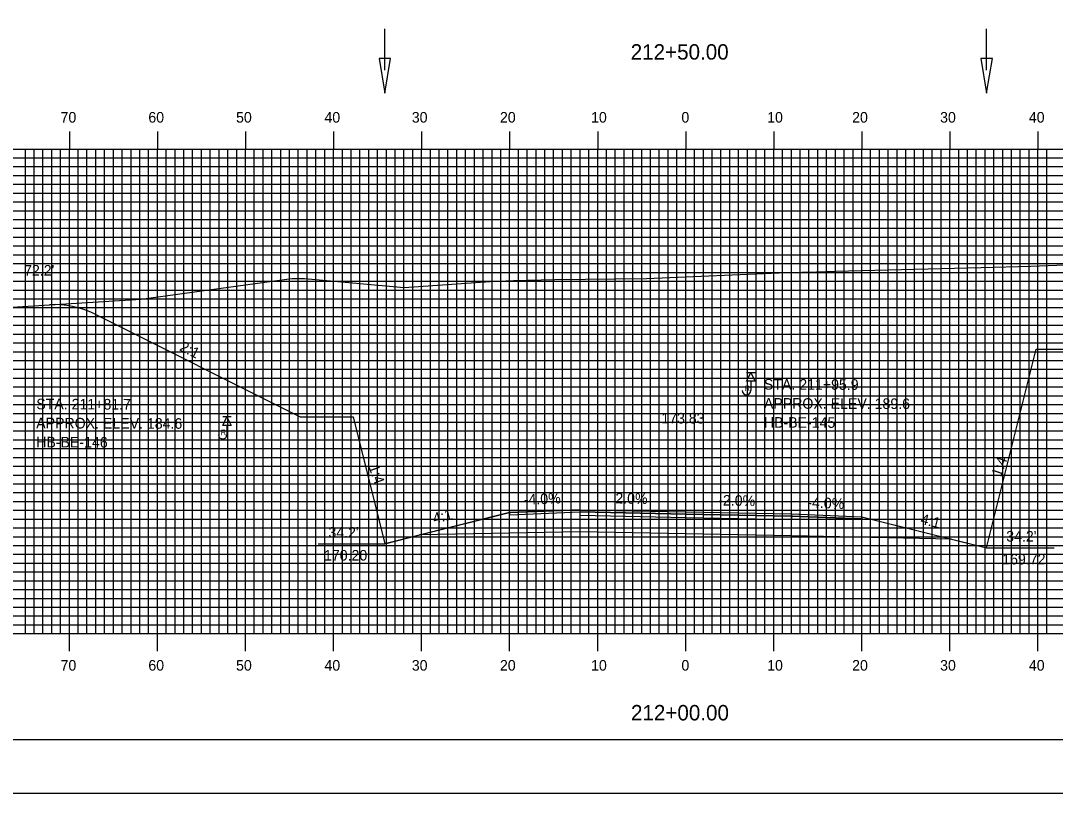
# Model space of a CAD drawing. Extents: x 1795240 to 1795583, y 442591 to 442811.
# Drawn here: x 1795329.8 to 1795447.3, y 442590.5 to 442678.2 of the extents above; entities that cross this region are included whole.
import ezdxf

# ---------------------------------------------------------------- set-up
doc = ezdxf.new("R2010")
doc.units = 0
for name, color, linetype in [('ANNOTATION', 7, 'Continuous'), ('BORDER', 7, 'Continuous'), ('BORING - REFUSAL', 7, 'Continuous'), ('D_Drainage_Ditch_Line', 7, 'Continuous'), ('D_Roadway_Centerline', 7, 'Continuous'), ('D_Roadway_Centerline_Text', 7, 'Continuous'), ('D_Roadway_Edge_Shoulder', 7, 'Continuous'), ('D_Roadway_Edge_TW', 7, 'Continuous'), ('D_Roadway_Pavement', 7, 'Continuous'), ('D_Roadway_SlopeLines', 7, 'Continuous'), ('D_Roadway_SubGrade', 7, 'Continuous'), ('D_Text_Standard', 7, 'Continuous'), ('H_V ANNOTATION', 7, 'Continuous'), ('MAJOR', 7, 'Continuous'), ('MINOR', 7, 'Continuous'), ('PDRAIN', 7, 'Continuous'), ('PLOT BOUNDARY', 7, 'Continuous'), ('S_Roadway_Centerline', 7, 'Continuous')]:
    doc.layers.add(name, color=color, linetype=linetype)

msp = doc.modelspace()

# ---------------------------------------------------------------- linework, layer by layer
at = {"layer": 'BORDER'}
msp.add_lwpolyline([(1795255.77, 442596.67), (1795575.77, 442596.67), (1795575.77, 442806.67), (1795255.77, 442806.67)], close=True, dxfattribs=at)
at = {"layer": 'BORING - REFUSAL'}
for p, q in [((1795413.25, 442638.27), (1795412.29, 442638.27)), ((1795412.77, 442637.31), (1795412.77, 442636.25)), ((1795353.75, 442633.27), (1795352.79, 442633.27)), ((1795353.27, 442632.31), (1795353.27, 442631.25))]:
    msp.add_line(p, q, dxfattribs=at)
for points in [[(1795412.77, 442638.27), (1795413.25, 442637.31), (1795412.29, 442637.31)], [(1795353.27, 442633.27), (1795353.75, 442632.31), (1795352.79, 442632.31)]]:
    msp.add_lwpolyline(points, close=True, dxfattribs=at)
for centre in [(1795412.28, 442636.25), (1795352.78, 442631.25)]:
    msp.add_arc(centre, 0.485, 180, 0, dxfattribs=at)
at = {"layer": 'D_Drainage_Ditch_Line'}
for p, q in [((1795371.19, 442672.63), (1795371.19, 442677.33)), ((1795439.54, 442672.63), (1795439.54, 442677.33))]:
    msp.add_line(p, q, dxfattribs=at)
for points in [[(1795371.85, 442673.94), (1795370.54, 442673.94), (1795371.19, 442670)], [(1795440.2, 442673.94), (1795438.88, 442673.94), (1795439.54, 442670)]]:
    msp.add_lwpolyline(points, close=True, dxfattribs=at)
at = {"layer": 'D_Roadway_Centerline'}
msp.add_lwpolyline([(1795338.22, 442644.95), (1795361.59, 442633.27), (1795367.59, 442633.27), (1795371.19, 442618.87), (1795375.19, 442619.87), (1795385.37, 442622.41), (1795393.37, 442622.73), (1795405.37, 442622.49), (1795417.37, 442622.25), (1795425.37, 442621.93), (1795435.54, 442619.39), (1795439.54, 442618.39), (1795445.18, 442640.97), (1795451.18, 442640.97), (1795470.79, 442650.77)], dxfattribs=at)
msp.add_arc((1795333.75, 442636.01), 10, 63.4349, 93.5916, dxfattribs=at)
at = {"layer": 'D_Roadway_Edge_Shoulder'}
for points in [[(1795393.37, 442622.73), (1795385.37, 442622.41), (1795385.37, 442622.16), (1795393.37, 442622.48)], [(1795417.37, 442622.25), (1795425.37, 442621.93), (1795425.37, 442621.68), (1795417.37, 442622)]]:
    msp.add_lwpolyline(points, close=True, dxfattribs=at)
at = {"layer": 'D_Roadway_Edge_TW'}
msp.add_lwpolyline([(1795393.37, 442622.48), (1795393.37, 442622.73), (1795405.37, 442622.49), (1795417.37, 442622.25), (1795417.37, 442622), (1795405.37, 442622.24)], close=True, dxfattribs=at)
at = {"layer": 'D_Roadway_Pavement'}
msp.add_lwpolyline([(1795393.37, 442622.07), (1795393.37, 442622.48), (1795405.37, 442622.24), (1795417.37, 442622), (1795417.37, 442621.59), (1795405.37, 442621.83)], close=True, dxfattribs=at)
at = {"layer": 'D_Roadway_SlopeLines'}
for points in [[(1795385.37, 442622.41), (1795371.19, 442618.87)], [(1795425.37, 442621.93), (1795439.54, 442618.39)]]:
    msp.add_lwpolyline(points, dxfattribs=at)
at = {"layer": 'D_Roadway_SubGrade'}
msp.add_lwpolyline([(1795393.37, 442620.23), (1795375.19, 442619.87), (1795385.37, 442622.41), (1795385.37, 442622.16), (1795393.37, 442622.48), (1795405.37, 442622.24), (1795417.37, 442622), (1795425.37, 442621.68), (1795425.37, 442621.93), (1795435.54, 442619.39), (1795417.37, 442619.75), (1795405.37, 442619.99)], close=True, dxfattribs=at)
at = {"layer": 'MAJOR'}
for p, q in [((1795335.37, 442665.67), (1795335.37, 442663.67)), ((1795345.37, 442665.67), (1795345.37, 442663.67)), ((1795355.37, 442665.67), (1795355.37, 442663.67)), ((1795365.37, 442665.67), (1795365.37, 442663.67)), ((1795375.37, 442665.67), (1795375.37, 442663.67)), ((1795385.37, 442665.67), (1795385.37, 442663.67)), ((1795395.37, 442665.67), (1795395.37, 442663.67)), ((1795405.37, 442665.67), (1795405.37, 442663.67)), ((1795415.37, 442665.67), (1795415.37, 442663.67)), ((1795425.37, 442665.67), (1795425.37, 442663.67)), ((1795435.37, 442665.67), (1795435.37, 442663.67)), ((1795445.37, 442665.67), (1795445.37, 442663.67)), ((1795265.37, 442663.67), (1795545.37, 442663.67)), ((1795265.37, 442663.67), (1795545.37, 442663.67)), ((1795335.37, 442608.67), (1795335.37, 442663.67)), ((1795345.37, 442608.67), (1795345.37, 442663.67)), ((1795355.37, 442608.67), (1795355.37, 442663.67)), ((1795365.37, 442608.67), (1795365.37, 442663.67)), ((1795375.37, 442608.67), (1795375.37, 442663.67)), ((1795385.37, 442608.67), (1795385.37, 442663.67)), ((1795395.37, 442608.67), (1795395.37, 442663.67)), ((1795405.37, 442608.67), (1795405.37, 442663.67)), ((1795415.37, 442608.67), (1795415.37, 442663.67)), ((1795425.37, 442608.67), (1795425.37, 442663.67)), ((1795435.37, 442608.67), (1795435.37, 442663.67)), ((1795445.37, 442608.67), (1795445.37, 442663.67)), ((1795265.37, 442658.67), (1795545.37, 442658.67)), ((1795265.37, 442653.67), (1795545.37, 442653.67)), ((1795265.37, 442648.67), (1795545.37, 442648.67)), ((1795265.37, 442643.67), (1795545.37, 442643.67)), ((1795265.37, 442638.67), (1795545.37, 442638.67)), ((1795265.37, 442633.67), (1795545.37, 442633.67)), ((1795265.37, 442628.67), (1795545.37, 442628.67)), ((1795265.37, 442623.67), (1795545.37, 442623.67)), ((1795265.37, 442618.67), (1795545.37, 442618.67)), ((1795265.37, 442613.67), (1795545.37, 442613.67)), ((1795265.37, 442608.67), (1795545.37, 442608.67)), ((1795265.37, 442608.67), (1795545.37, 442608.67)), ((1795335.37, 442606.66), (1795335.37, 442608.67)), ((1795345.37, 442606.66), (1795345.37, 442608.67)), ((1795355.37, 442606.66), (1795355.37, 442608.67)), ((1795365.37, 442606.66), (1795365.37, 442608.67)), ((1795375.37, 442606.66), (1795375.37, 442608.67)), ((1795385.37, 442606.66), (1795385.37, 442608.67)), ((1795395.37, 442606.66), (1795395.37, 442608.67)), ((1795405.37, 442606.66), (1795405.37, 442608.67)), ((1795415.37, 442606.66), (1795415.37, 442608.67)), ((1795425.37, 442606.66), (1795425.37, 442608.67)), ((1795435.37, 442606.66), (1795435.37, 442608.67)), ((1795445.37, 442606.66), (1795445.37, 442608.67))]:
    msp.add_line(p, q, dxfattribs=at)
at = {"layer": 'MINOR'}
for p, q in [((1795330.37, 442608.67), (1795330.37, 442663.67)), ((1795331.37, 442608.67), (1795331.37, 442663.67)), ((1795332.37, 442608.67), (1795332.37, 442663.67)), ((1795333.37, 442608.67), (1795333.37, 442663.67)), ((1795334.37, 442608.67), (1795334.37, 442663.67)), ((1795336.37, 442608.67), (1795336.37, 442663.67)), ((1795337.37, 442608.67), (1795337.37, 442663.67)), ((1795338.37, 442608.67), (1795338.37, 442663.67)), ((1795339.37, 442608.67), (1795339.37, 442663.67)), ((1795340.37, 442608.67), (1795340.37, 442663.67)), ((1795341.37, 442608.67), (1795341.37, 442663.67)), ((1795342.37, 442608.67), (1795342.37, 442663.67)), ((1795343.37, 442608.67), (1795343.37, 442663.67)), ((1795344.37, 442608.67), (1795344.37, 442663.67)), ((1795346.37, 442608.67), (1795346.37, 442663.67)), ((1795347.37, 442608.67), (1795347.37, 442663.67)), ((1795348.37, 442608.67), (1795348.37, 442663.67)), ((1795349.37, 442608.67), (1795349.37, 442663.67)), ((1795350.37, 442608.67), (1795350.37, 442663.67)), ((1795351.37, 442608.67), (1795351.37, 442663.67)), ((1795352.37, 442608.67), (1795352.37, 442663.67)), ((1795353.37, 442608.67), (1795353.37, 442663.67)), ((1795354.37, 442608.67), (1795354.37, 442663.67)), ((1795356.37, 442608.67), (1795356.37, 442663.67)), ((1795357.37, 442608.67), (1795357.37, 442663.67)), ((1795358.37, 442608.67), (1795358.37, 442663.67)), ((1795359.37, 442608.67), (1795359.37, 442663.67)), ((1795360.37, 442608.67), (1795360.37, 442663.67)), ((1795361.37, 442608.67), (1795361.37, 442663.67)), ((1795362.37, 442608.67), (1795362.37, 442663.67)), ((1795363.37, 442608.67), (1795363.37, 442663.67)), ((1795364.37, 442608.67), (1795364.37, 442663.67)), ((1795366.37, 442608.67), (1795366.37, 442663.67)), ((1795367.37, 442608.67), (1795367.37, 442663.67)), ((1795368.37, 442608.67), (1795368.37, 442663.67)), ((1795369.37, 442608.67), (1795369.37, 442663.67)), ((1795370.37, 442608.67), (1795370.37, 442663.67)), ((1795371.37, 442608.67), (1795371.37, 442663.67)), ((1795372.37, 442608.67), (1795372.37, 442663.67)), ((1795373.37, 442608.67), (1795373.37, 442663.67)), ((1795374.37, 442608.67), (1795374.37, 442663.67)), ((1795376.37, 442608.67), (1795376.37, 442663.67)), ((1795377.37, 442608.67), (1795377.37, 442663.67)), ((1795378.37, 442608.67), (1795378.37, 442663.67)), ((1795379.37, 442608.67), (1795379.37, 442663.67)), ((1795380.37, 442608.67), (1795380.37, 442663.67)), ((1795381.37, 442608.67), (1795381.37, 442663.67)), ((1795382.37, 442608.67), (1795382.37, 442663.67)), ((1795383.37, 442608.67), (1795383.37, 442663.67)), ((1795384.37, 442608.67), (1795384.37, 442663.67)), ((1795386.37, 442608.67), (1795386.37, 442663.67)), ((1795387.37, 442608.67), (1795387.37, 442663.67)), ((1795388.37, 442608.67), (1795388.37, 442663.67)), ((1795389.37, 442608.67), (1795389.37, 442663.67)), ((1795390.37, 442608.67), (1795390.37, 442663.67)), ((1795391.37, 442608.67), (1795391.37, 442663.67)), ((1795392.37, 442608.67), (1795392.37, 442663.67)), ((1795393.37, 442608.67), (1795393.37, 442663.67)), ((1795394.37, 442608.67), (1795394.37, 442663.67)), ((1795396.37, 442608.67), (1795396.37, 442663.67)), ((1795397.37, 442608.67), (1795397.37, 442663.67)), ((1795398.37, 442608.67), (1795398.37, 442663.67)), ((1795399.37, 442608.67), (1795399.37, 442663.67)), ((1795400.37, 442608.67), (1795400.37, 442663.67)), ((1795401.37, 442608.67), (1795401.37, 442663.67)), ((1795402.37, 442608.67), (1795402.37, 442663.67)), ((1795403.37, 442608.67), (1795403.37, 442663.67)), ((1795404.37, 442608.67), (1795404.37, 442663.67)), ((1795406.37, 442608.67), (1795406.37, 442663.67)), ((1795407.37, 442608.67), (1795407.37, 442663.67)), ((1795408.37, 442608.67), (1795408.37, 442663.67)), ((1795409.37, 442608.67), (1795409.37, 442663.67)), ((1795410.37, 442608.67), (1795410.37, 442663.67)), ((1795411.37, 442608.67), (1795411.37, 442663.67)), ((1795412.37, 442608.67), (1795412.37, 442663.67)), ((1795413.37, 442608.67), (1795413.37, 442663.67)), ((1795414.37, 442608.67), (1795414.37, 442663.67)), ((1795416.37, 442608.67), (1795416.37, 442663.67)), ((1795417.37, 442608.67), (1795417.37, 442663.67)), ((1795418.37, 442608.67), (1795418.37, 442663.67)), ((1795419.37, 442608.67), (1795419.37, 442663.67)), ((1795420.37, 442608.67), (1795420.37, 442663.67)), ((1795421.37, 442608.67), (1795421.37, 442663.67)), ((1795422.37, 442608.67), (1795422.37, 442663.67)), ((1795423.37, 442608.67), (1795423.37, 442663.67)), ((1795424.37, 442608.67), (1795424.37, 442663.67)), ((1795426.37, 442608.67), (1795426.37, 442663.67)), ((1795427.37, 442608.67), (1795427.37, 442663.67)), ((1795428.37, 442608.67), (1795428.37, 442663.67)), ((1795429.37, 442608.67), (1795429.37, 442663.67)), ((1795430.37, 442608.67), (1795430.37, 442663.67)), ((1795431.37, 442608.67), (1795431.37, 442663.67)), ((1795432.37, 442608.67), (1795432.37, 442663.67)), ((1795433.37, 442608.67), (1795433.37, 442663.67)), ((1795434.37, 442608.67), (1795434.37, 442663.67)), ((1795436.37, 442608.67), (1795436.37, 442663.67)), ((1795437.37, 442608.67), (1795437.37, 442663.67)), ((1795438.37, 442608.67), (1795438.37, 442663.67)), ((1795439.37, 442608.67), (1795439.37, 442663.67)), ((1795440.37, 442608.67), (1795440.37, 442663.67)), ((1795441.37, 442608.67), (1795441.37, 442663.67)), ((1795442.37, 442608.67), (1795442.37, 442663.67)), ((1795443.37, 442608.67), (1795443.37, 442663.67)), ((1795444.37, 442608.67), (1795444.37, 442663.67)), ((1795446.37, 442608.67), (1795446.37, 442663.67)), ((1795265.37, 442662.67), (1795545.37, 442662.67)), ((1795265.37, 442661.67), (1795545.37, 442661.67)), ((1795265.37, 442660.67), (1795545.37, 442660.67)), ((1795265.37, 442659.67), (1795545.37, 442659.67)), ((1795265.37, 442657.67), (1795545.37, 442657.67)), ((1795265.37, 442656.67), (1795545.37, 442656.67)), ((1795265.37, 442655.67), (1795545.37, 442655.67)), ((1795265.37, 442654.67), (1795545.37, 442654.67)), ((1795265.37, 442652.67), (1795545.37, 442652.67)), ((1795265.37, 442651.67), (1795545.37, 442651.67)), ((1795265.37, 442650.67), (1795545.37, 442650.67)), ((1795265.37, 442649.67), (1795545.37, 442649.67)), ((1795265.37, 442647.67), (1795545.37, 442647.67)), ((1795265.37, 442646.67), (1795545.37, 442646.67)), ((1795265.37, 442645.67), (1795545.37, 442645.67)), ((1795265.37, 442644.67), (1795545.37, 442644.67)), ((1795265.37, 442642.67), (1795545.37, 442642.67)), ((1795265.37, 442641.67), (1795545.37, 442641.67)), ((1795265.37, 442640.67), (1795545.37, 442640.67)), ((1795265.37, 442639.67), (1795545.37, 442639.67)), ((1795265.37, 442637.67), (1795545.37, 442637.67)), ((1795265.37, 442636.67), (1795545.37, 442636.67)), ((1795265.37, 442635.67), (1795545.37, 442635.67)), ((1795265.37, 442634.67), (1795545.37, 442634.67)), ((1795265.37, 442632.67), (1795545.37, 442632.67)), ((1795265.37, 442631.67), (1795545.37, 442631.67)), ((1795265.37, 442630.67), (1795545.37, 442630.67)), ((1795265.37, 442629.67), (1795545.37, 442629.67)), ((1795265.37, 442627.67), (1795545.37, 442627.67)), ((1795265.37, 442626.67), (1795545.37, 442626.67)), ((1795265.37, 442625.67), (1795545.37, 442625.67)), ((1795265.37, 442624.67), (1795545.37, 442624.67)), ((1795265.37, 442622.67), (1795545.37, 442622.67)), ((1795265.37, 442621.67), (1795545.37, 442621.67)), ((1795265.37, 442620.67), (1795545.37, 442620.67)), ((1795265.37, 442619.67), (1795545.37, 442619.67)), ((1795265.37, 442617.67), (1795545.37, 442617.67)), ((1795265.37, 442616.67), (1795545.37, 442616.67)), ((1795265.37, 442615.67), (1795545.37, 442615.67)), ((1795265.37, 442614.67), (1795545.37, 442614.67)), ((1795265.37, 442612.67), (1795545.37, 442612.67)), ((1795265.37, 442611.67), (1795545.37, 442611.67)), ((1795265.37, 442610.67), (1795545.37, 442610.67)), ((1795265.37, 442609.67), (1795545.37, 442609.67))]:
    msp.add_line(p, q, dxfattribs=at)
at = {"layer": 'PDRAIN'}
for p, q in [((1795363.63, 442618.87), (1795371.19, 442618.87)), ((1795439.54, 442618.39), (1795447.23, 442618.39))]:
    msp.add_line(p, q, dxfattribs=at)
at = {"layer": 'PLOT BOUNDARY'}
msp.add_lwpolyline([(1795239.58, 442590.55), (1795579.58, 442590.55), (1795579.58, 442810.55), (1795239.58, 442810.55)], close=True, dxfattribs=at)
at = {"layer": 'S_Roadway_Centerline'}
msp.add_lwpolyline([(1795326.99, 442645.6), (1795343.54, 442646.64), (1795358.39, 442648.69), (1795360.65, 442648.96), (1795362.08, 442648.98), (1795373.39, 442647.97), (1795383.15, 442648.62), (1795385.8, 442648.75), (1795390.51, 442648.87), (1795400.92, 442648.98), (1795416.85, 442649.64), (1795420.24, 442649.72), (1795422.34, 442649.82), (1795438.91, 442650.24), (1795444.55, 442650.36), (1795454.36, 442650.74)], dxfattribs=at)

# ---------------------------------------------------------------- texts
at = {"layer": 'ANNOTATION'}
for s, rotation, p in [('2:1', 333.4349, (1795347.79, 442640.85)), ('1:4', 70.516, (1795441.18, 442626.38)), ('1:4', 289.484, (1795369.33, 442627.61)), ('-4.0%', 2.2906, (1795387, 442623.28)), ('2.0%', 358.8542, (1795397.37, 442623.45)), ('-2.0%', 358.8542, (1795409.05, 442623.22)), ('-4.0%', 357.7094, (1795419.16, 442622.98)), ('4:1', 14.0362, (1795376.81, 442621.14)), ('4:1', 345.9638, (1795431.96, 442621.15))]:
    msp.add_text(s, height=1.2, rotation=rotation, dxfattribs=at).set_placement(p)
for s, p in [("34.2'", (1795364.79, 442619.56)), ("34.2'", (1795441.77, 442619.12)), ('170.20', (1795364.29, 442616.96)), ('169.72', (1795441.32, 442616.52))]:
    msp.add_text(s, height=1.2, dxfattribs=at).set_placement(p)
at = {"layer": 'BORING - REFUSAL'}
for p in [(1795412.06, 442636.19), (1795352.56, 442631.19)]:
    msp.add_text('R', height=0.64, dxfattribs=at).set_placement(p)
for s, p in [('STA. 211+95.9', (1795414.25, 442636.37)), ('STA. 211+81.7', (1795331.61, 442634.13)), ('APPROX. ELEV. 189.6', (1795414.25, 442634.21)), ('APPROX. ELEV. 184.6', (1795331.6, 442631.97)), ('HB-BE-145', (1795414.24, 442632.05)), ('HB-BE-146', (1795331.6, 442629.81))]:
    msp.add_text(s, height=1.2, rotation=359.8142, dxfattribs=at).set_placement(p)
at = {"layer": 'D_Roadway_Centerline'}
for s, p in [('C', (1795405.36, 442622.49)), ('L', (1795405.37, 442622.49))]:
    msp.add_text(s, height=0.0146, dxfattribs=at).set_placement(p)
at = {"layer": 'D_Roadway_Centerline_Text'}
msp.add_text('173.83', height=1.2, dxfattribs=at).set_placement((1795402.6, 442632.52))
at = {"layer": 'D_Text_Standard'}
msp.add_text("72.2'", height=1.2, dxfattribs=at).set_placement((1795330.23, 442649.3))
at = {"layer": 'H_V ANNOTATION'}
for s, height, p in [('212+50.00', 1.75, (1795399.12, 442673.82)), ('70', 1.2, (1795334.37, 442666.67)), ('60', 1.2, (1795344.34, 442666.67)), ('50', 1.2, (1795354.3, 442666.67)), ('40', 1.2, (1795364.34, 442666.67)), ('30', 1.2, (1795374.26, 442666.67)), ('20', 1.2, (1795384.27, 442666.67)), ('10', 1.2, (1795394.62, 442666.67)), ('0', 1.2, (1795404.88, 442666.67)), ('10', 1.2, (1795414.62, 442666.67)), ('20', 1.2, (1795424.27, 442666.67)), ('30', 1.2, (1795434.26, 442666.67)), ('40', 1.2, (1795444.34, 442666.67)), ('70', 1.2, (1795334.37, 442604.47)), ('60', 1.2, (1795344.34, 442604.47)), ('50', 1.2, (1795354.3, 442604.47)), ('40', 1.2, (1795364.34, 442604.47)), ('30', 1.2, (1795374.26, 442604.47)), ('20', 1.2, (1795384.27, 442604.47)), ('10', 1.2, (1795394.62, 442604.47)), ('0', 1.2, (1795404.88, 442604.47)), ('10', 1.2, (1795414.62, 442604.47)), ('20', 1.2, (1795424.27, 442604.47)), ('30', 1.2, (1795434.26, 442604.47)), ('40', 1.2, (1795444.34, 442604.47)), ('212+00.00', 1.75, (1795399.15, 442598.82))]:
    msp.add_text(s, height=height, dxfattribs=at).set_placement(p)

doc.saveas('drawing.dxf')
